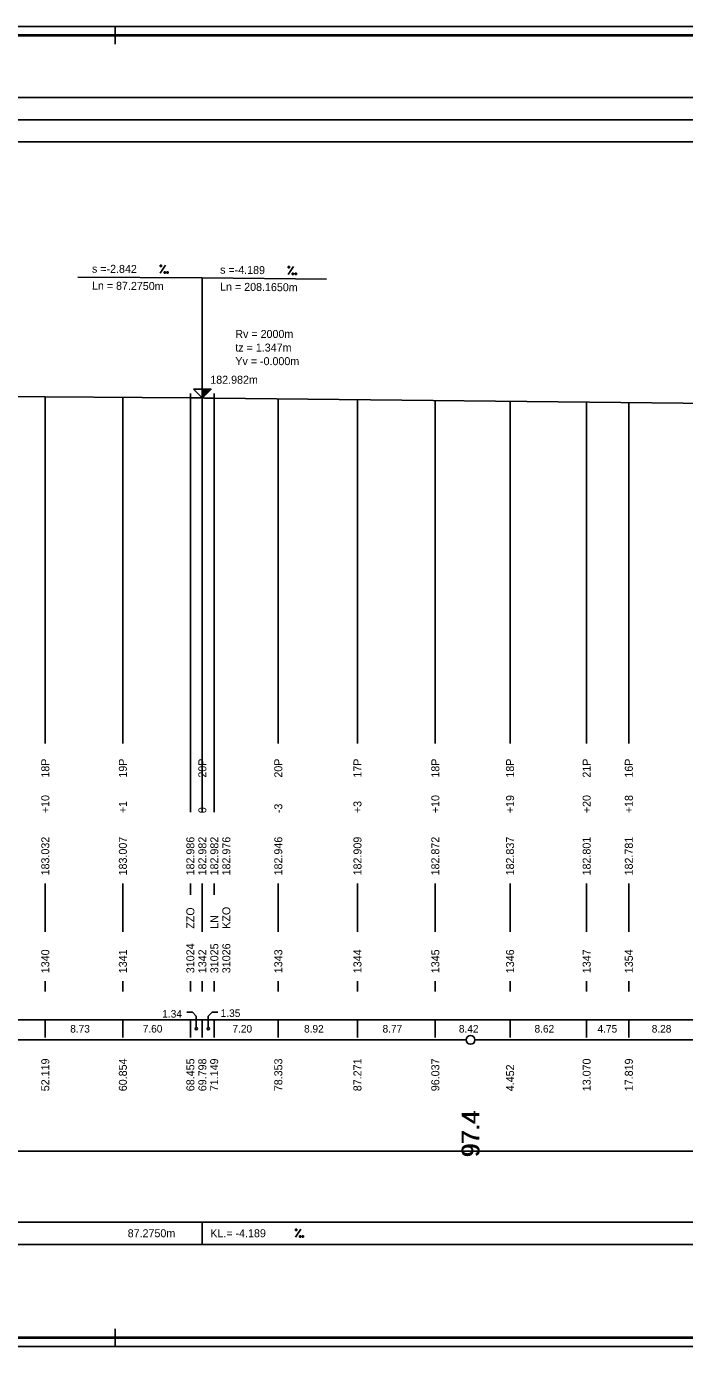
# Model space of a CAD drawing. Extents: x 0 to 10087, y -805 to 297.
# Drawn here: x 2080 to 2228.2, y 0 to 297 of the extents above; entities that cross this region are included whole.
import ezdxf

# ---------------------------------------------------------------- set-up
doc = ezdxf.new("R2010")
doc.units = 0
for name, color, linetype in [('CARKY_HODNOT', 7, 'Continuous'), ('KRIV1_CARA', 7, 'Continuous'), ('NIVELETA_CARA', 7, 'Continuous'), ('NIVELETA_TEXT', 7, 'Continuous'), ('RAM', 7, 'Continuous'), ('REZERVA', 7, 'Continuous'), ('STAN_CARA', 7, 'Continuous'), ('STAN_PAS', 7, 'Continuous'), ('STAN_TEXT', 7, 'Continuous'), ('TEXT', 7, 'Continuous'), ('TXT_C_BODU', 7, 'Continuous')]:
    doc.layers.add(name, color=color, linetype=linetype)

msp = doc.modelspace()

# ---------------------------------------------------------------- linework, layer by layer
at = {"layer": 'CARKY_HODNOT'}
for p, q in [((2084.24, 138.35), (2084.24, 213.66)), ((2101.71, 138.35), (2101.71, 213.54)), ((2116.91, 138.35), (2116.91, 213.43)), ((2119.6, 138.35), (2119.6, 213.41)), ((2119.6, 138.35), (2119.6, 213.41)), ((2122.3, 138.35), (2122.3, 213.38)), ((2136.71, 138.35), (2136.71, 213.23)), ((2154.54, 138.35), (2154.54, 213.04)), ((2172.07, 138.35), (2172.07, 212.86)), ((2188.9, 138.35), (2188.9, 212.68)), ((2206.14, 138.35), (2206.14, 212.5)), ((2215.64, 138.35), (2215.64, 212.4)), ((2084.24, 135.65), (2084.24, 138.35)), ((2101.71, 135.65), (2101.71, 138.35)), ((2116.91, 126.2), (2116.91, 138.35)), ((2119.6, 135.65), (2119.6, 138.35)), ((2119.6, 126.2), (2119.6, 138.35)), ((2122.3, 126.2), (2122.3, 138.35)), ((2136.71, 135.65), (2136.71, 138.35)), ((2154.54, 135.65), (2154.54, 138.35)), ((2172.07, 135.65), (2172.07, 138.35)), ((2188.9, 135.65), (2188.9, 138.35)), ((2206.14, 135.65), (2206.14, 138.35)), ((2215.64, 135.65), (2215.64, 138.35)), ((2116.91, 120.25), (2116.91, 126.2)), ((2119.6, 124.35), (2119.6, 126.2)), ((2119.6, 120.25), (2119.6, 126.2)), ((2122.3, 120.25), (2122.3, 126.2)), ((2084.24, 93.3), (2084.24, 104.2)), ((2101.71, 93.3), (2101.71, 104.2)), ((2116.91, 101.65), (2116.91, 104.2)), ((2119.6, 93.3), (2119.6, 104.2)), ((2119.6, 100), (2119.6, 104.2)), ((2122.3, 101.65), (2122.3, 104.2)), ((2136.71, 93.3), (2136.71, 104.2)), ((2154.54, 93.3), (2154.54, 104.2)), ((2172.07, 93.3), (2172.07, 104.2)), ((2188.9, 93.3), (2188.9, 104.2)), ((2206.14, 93.3), (2206.14, 104.2)), ((2215.64, 93.3), (2215.64, 104.2)), ((2084.24, 79.9), (2084.24, 82.2)), ((2101.71, 79.9), (2101.71, 82.2)), ((2116.91, 79.9), (2116.91, 82.2)), ((2119.6, 79.9), (2119.6, 82.2)), ((2119.6, 79.9), (2119.6, 82.2)), ((2122.3, 79.9), (2122.3, 82.2)), ((2136.71, 79.9), (2136.71, 82.2)), ((2154.54, 79.9), (2154.54, 82.2)), ((2172.07, 79.9), (2172.07, 82.2)), ((2188.9, 79.9), (2188.9, 82.2)), ((2206.14, 79.9), (2206.14, 82.2)), ((2215.64, 79.9), (2215.64, 82.2))]:
    msp.add_line(p, q, dxfattribs=at)
at = {"layer": 'KRIV1_CARA'}
msp.add_line((2066.11, 44), (2477.23, 44), dxfattribs=at)
at = {"layer": 'NIVELETA_CARA'}
for p, q in [((300, 281), (8321.33, 281)), ((300, 276), (8321.33, 276)), ((300, 271), (8321.33, 271)), ((2119.6, 240.41), (2091.6, 240.61)), ((2119.6, 213.41), (2119.6, 240.41)), ((2119.6, 240.41), (2147.6, 240.12)), ((1960.59, 214.54), (2116.91, 213.43)), ((2116.91, 213.43), (2116.91, 214.43)), ((2119.6, 213.41), (2117.6, 215.41)), ((2117.6, 215.41), (2121.6, 215.41)), ((2119.6, 213.41), (2119.6, 215.41)), ((2121.6, 215.41), (2119.6, 213.41)), ((2119.67, 213.48), (2119.67, 215.41)), ((2119.74, 213.54), (2119.74, 215.41)), ((2119.8, 213.61), (2119.8, 215.41)), ((2119.87, 213.68), (2119.87, 215.41)), ((2119.94, 213.74), (2119.94, 215.41)), ((2120, 213.81), (2120, 215.41)), ((2120.07, 213.88), (2120.07, 215.41)), ((2120.14, 213.94), (2120.14, 215.41)), ((2120.2, 214.01), (2120.2, 215.41)), ((2120.27, 214.08), (2120.27, 215.41)), ((2120.34, 214.14), (2120.34, 215.41)), ((2120.4, 214.21), (2120.4, 215.41)), ((2120.47, 214.28), (2120.47, 215.41)), ((2120.54, 214.34), (2120.54, 215.41)), ((2120.6, 214.41), (2120.6, 215.41)), ((2120.67, 214.48), (2120.67, 215.41)), ((2120.74, 214.54), (2120.74, 215.41)), ((2120.8, 214.61), (2120.8, 215.41)), ((2120.87, 214.68), (2120.87, 215.41)), ((2120.94, 214.74), (2120.94, 215.41)), ((2121, 214.81), (2121, 215.41)), ((2121.07, 214.88), (2121.07, 215.41)), ((2121.14, 214.94), (2121.14, 215.41)), ((2121.2, 215.01), (2121.2, 215.41)), ((2121.27, 215.08), (2121.27, 215.41)), ((2121.34, 215.14), (2121.34, 215.41)), ((2121.4, 215.21), (2121.4, 215.41)), ((2121.47, 215.28), (2121.47, 215.41)), ((2121.54, 215.34), (2121.54, 215.41)), ((2122.3, 213.38), (2122.3, 214.38)), ((2116.91, 213.43), (2119.6, 213.41)), ((2116.91, 213.43), (2117.41, 213.43)), ((2117.41, 213.43), (2117.91, 213.42)), ((2117.91, 213.42), (2118.41, 213.42)), ((2118.41, 213.42), (2118.91, 213.41)), ((2118.91, 213.41), (2119.41, 213.41)), ((2119.41, 213.41), (2119.6, 213.41)), ((2119.6, 213.41), (2122.3, 213.38)), ((2119.6, 213.41), (2120.1, 213.4)), ((2120.1, 213.4), (2120.6, 213.4)), ((2120.6, 213.4), (2121.1, 213.39)), ((2121.1, 213.39), (2121.6, 213.39)), ((2121.6, 213.39), (2122.1, 213.38)), ((2122.1, 213.38), (2122.3, 213.38)), ((2122.3, 213.38), (2531.93, 209.09)), ((500, 28), (8321.33, 28)), ((2119.6, 23), (2119.6, 28)), ((500, 23), (8321.33, 23))]:
    msp.add_line(p, q, dxfattribs=at)
at = {"layer": 'NIVELETA_TEXT'}
for p, q in [((2110.11, 241.48), (2111.31, 243.27)), ((2110.12, 243.27), (2110.12, 242.98)), ((2110.42, 243.27), (2110.12, 243.27)), ((2110.12, 243.27), (2110.12, 243.27)), ((2110.12, 242.98), (2110.41, 242.97)), ((2110.41, 242.97), (2110.42, 243.27)), ((2111.02, 241.77), (2111.01, 241.47)), ((2111.01, 241.47), (2111.31, 241.47)), ((2111.31, 241.77), (2111.02, 241.77)), ((2111.02, 241.77), (2111.02, 241.76)), ((2111.31, 241.47), (2111.31, 241.77)), ((2111.63, 241.77), (2111.63, 241.47)), ((2111.64, 241.77), (2111.63, 241.76)), ((2111.63, 241.47), (2111.93, 241.47)), ((2111.93, 241.76), (2111.64, 241.77)), ((2111.93, 241.47), (2111.93, 241.76)), ((2138.96, 241.21), (2140.16, 242.99)), ((2138.97, 243), (2138.97, 242.71)), ((2138.98, 243), (2138.97, 243)), ((2138.97, 242.71), (2139.27, 242.7)), ((2139.27, 243), (2138.98, 243)), ((2139.27, 242.7), (2139.27, 243)), ((2139.87, 241.5), (2139.86, 241.2)), ((2139.86, 241.2), (2140.16, 241.2)), ((2140.16, 241.49), (2139.87, 241.5)), ((2139.87, 241.5), (2139.87, 241.49)), ((2140.16, 241.2), (2140.16, 241.49)), ((2140.48, 241.49), (2140.48, 241.19)), ((2140.49, 241.49), (2140.48, 241.49)), ((2140.48, 241.19), (2140.78, 241.19)), ((2140.78, 241.49), (2140.49, 241.49)), ((2140.78, 241.19), (2140.78, 241.49)), ((2140.56, 24.6), (2141.75, 26.4)), ((2140.56, 26.4), (2140.56, 26.1)), ((2140.85, 26.4), (2140.56, 26.4)), ((2140.56, 26.4), (2140.56, 26.39)), ((2140.56, 26.1), (2140.85, 26.1)), ((2140.85, 26.1), (2140.85, 26.4)), ((2141.47, 24.9), (2141.47, 24.6)), ((2141.76, 24.9), (2141.47, 24.9)), ((2141.47, 24.9), (2141.47, 24.89)), ((2141.47, 24.6), (2141.76, 24.6)), ((2141.76, 24.6), (2141.76, 24.9)), ((2142.08, 24.9), (2142.08, 24.6)), ((2142.38, 24.9), (2142.08, 24.9)), ((2142.08, 24.9), (2142.08, 24.89)), ((2142.08, 24.6), (2142.38, 24.6)), ((2142.38, 24.6), (2142.38, 24.9))]:
    msp.add_line(p, q, dxfattribs=at)
at = {"layer": 'RAM'}
for p, q in [((8636.33, 297), (0, 297)), ((2100, 293), (2100, 297)), ((8634.33, 295.1), (2, 295.1)), ((8634.33, 295), (2, 295)), ((8634.33, 294.9), (2, 294.9)), ((2100, 0), (2100, 4)), ((0, 0), (8636.33, 0)), ((2, 2.1), (8634.33, 2.1)), ((2, 2), (8634.33, 2)), ((2, 1.9), (8634.33, 1.9))]:
    msp.add_line(p, q, dxfattribs=at)
at = {"layer": 'REZERVA'}
msp.add_circle((2180, 69), 1, dxfattribs=at)
at = {"layer": 'STAN_CARA'}
for p, q in [((1981, 69), (2179, 69)), ((2181, 69), (2379, 69))]:
    msp.add_line(p, q, dxfattribs=at)
at = {"layer": 'STAN_PAS'}
for p, q in [((2117.4, 75.2), (2116.13, 75.2)), ((2118.25, 74.35), (2117.4, 75.2)), ((2118.25, 71.75), (2118.25, 74.35)), ((2120.95, 74.35), (2121.8, 75.2)), ((2120.95, 71.75), (2120.95, 74.35)), ((2121.8, 75.2), (2123.08, 75.2)), ((300, 73.5), (8321.33, 73.5)), ((2084.24, 69.5), (2084.24, 73.5)), ((2101.71, 69.5), (2101.71, 73.5)), ((2116.91, 69.5), (2116.91, 73.5)), ((2119.6, 69.5), (2119.6, 73.5)), ((2119.6, 69.5), (2119.6, 73.5)), ((2122.3, 69.5), (2122.3, 73.5)), ((2136.71, 69.5), (2136.71, 73.5)), ((2154.54, 69.5), (2154.54, 73.5)), ((2172.07, 69.5), (2172.07, 73.5)), ((2188.9, 69.5), (2188.9, 73.5)), ((2206.14, 69.5), (2206.14, 73.5)), ((2215.64, 69.5), (2215.64, 73.5))]:
    msp.add_line(p, q, dxfattribs=at)
for centre in [(2118.25, 71.5), (2120.95, 71.5)]:
    msp.add_circle(centre, 0.25, dxfattribs=at)

# ---------------------------------------------------------------- texts
at = {"layer": 'NIVELETA_TEXT'}
for s, rotation, p in [('s =-2.842', 359.593, (2094.75, 241.59)), ('s =-4.189', 359.4, (2123.6, 241.37)), ('Ln = 87.2750m', 359.593, (2094.75, 237.79)), ('Ln = 208.1650m', 359.4, (2123.6, 237.57))]:
    msp.add_text(s, height=1.8, rotation=rotation, dxfattribs=at).set_placement(p)
for s, p in [('Rv = 2000m', (2127.04, 226.91)), ('tz = 1.347m', (2127.04, 223.85)), ('Yv = -0.000m', (2127.04, 220.79)), ('182.982m', (2121.4, 216.61)), ('87.2750m', (2102.8, 24.6)), ('KL.= -4.189', (2121.4, 24.6))]:
    msp.add_text(s, height=1.8, dxfattribs=at).set_placement(p)
at = {"layer": 'STAN_TEXT'}
for s, p in [('1.34', (2110.59, 74.01)), ('1.35', (2123.74, 74.16)), ('8.73', (2089.86, 70.65)), ('7.60', (2106.19, 70.65)), ('7.20', (2126.39, 70.65)), ('8.92', (2142.51, 70.65)), ('8.77', (2160.19, 70.65)), ('8.42', (2177.37, 70.65)), ('8.62', (2194.41, 70.65)), ('4.75', (2208.6, 70.64)), ('8.28', (2220.8, 70.65))]:
    msp.add_text(s, height=1.7, dxfattribs=at).set_placement(p)
for s, height, p in [('52.119', 1.8, (2085.14, 57.45)), ('60.854', 1.8, (2102.61, 57.45)), ('68.455', 1.8, (2117.81, 57.45)), ('69.798', 1.8, (2120.51, 57.45)), ('71.149', 1.8, (2123.17, 57.45)), ('78.353', 1.8, (2137.61, 57.45)), ('87.271', 1.8, (2155.44, 57.45)), ('96.037', 1.8, (2172.97, 57.45)), ('4.452', 1.8, (2189.8, 57.45)), ('13.070', 1.8, (2207.04, 57.45)), ('17.819', 1.8, (2216.54, 57.45)), ('    97.4', 4, (2182, 36.84)), ('    97.4', 4, (2182, 36.74)), ('    97.4', 4, (2182, 36.64))]:
    msp.add_text(s, height=height, rotation=90, dxfattribs=at).set_placement(p)
at = {"layer": 'TEXT'}
for s, p in [('18P', (2085.14, 128)), ('19P', (2102.61, 128)), ('20P', (2120.51, 128)), ('20P', (2137.61, 128)), ('17P', (2155.44, 128)), ('18P', (2172.97, 128)), ('18P', (2189.8, 128)), ('21P', (2207.04, 128)), ('16P', (2216.54, 128)), ('+10', (2085.14, 120)), ('+1', (2102.61, 120)), ('-3', (2137.61, 120)), ('+3', (2155.44, 120)), ('+10', (2172.97, 120)), ('+19', (2189.8, 120)), ('+20', (2207.04, 120)), ('+18', (2216.54, 120)), ('0', (2120.51, 120)), ('183.032', (2085.14, 106)), ('183.007', (2102.61, 106)), ('182.986', (2117.81, 106)), ('182.982', (2120.51, 106)), ('182.982', (2123.21, 106)), ('182.976', (2125.91, 106)), ('182.946', (2137.61, 106)), ('182.909', (2155.44, 106)), ('182.872', (2172.97, 106)), ('182.837', (2189.8, 106)), ('182.801', (2207.04, 106)), ('182.781', (2216.54, 106)), ('ZZO', (2117.81, 94)), ('KZO', (2125.91, 94)), ('LN', (2123.21, 94))]:
    msp.add_text(s, height=1.8, rotation=90, dxfattribs=at).set_placement(p)
at = {"layer": 'TXT_C_BODU'}
for s, p in [('1340', (2085.14, 84)), ('1341', (2102.61, 84)), ('31024', (2117.81, 84)), ('1342', (2120.51, 84)), ('31025', (2123.21, 84)), ('31026', (2125.91, 84)), ('1343', (2137.61, 84)), ('1344', (2155.44, 84)), ('1345', (2172.97, 84)), ('1346', (2189.8, 84)), ('1347', (2207.04, 84)), ('1354', (2216.54, 84))]:
    msp.add_text(s, height=1.8, rotation=90, dxfattribs=at).set_placement(p)

doc.saveas('drawing.dxf')
